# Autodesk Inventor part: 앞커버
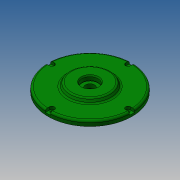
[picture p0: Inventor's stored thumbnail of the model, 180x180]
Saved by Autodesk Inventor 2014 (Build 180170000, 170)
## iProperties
Created: 2016-11
Part Number: 앞커버
Material: 알루미늄 6061
Document SubType Name: Modeling
Designer: mduedu
Density: 2.71 g/cm^3
Mass: 394.831 g
Surface Area: 366.671 cm^2
Volume: 145.694 cm^3
Appearance: 진녹색
Author: mduedu
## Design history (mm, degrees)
sketch "스케치1"
  geometry: L1 (22, -12.5)-(22, -30); L2 (22, -30)-(16, -33.464); L3 (16, -33.464)-(16, -65); L4 (16, -65)-(8, -65); L5 (8, -65)-(8, -53); L6 (8, -53)-(0, -53); L7 (0, -53)-(0, -14); L8 (0, 0)-(22, 0); L9 (8, -14)-(8, -7); L10 (8, -7)-(14.5, -7); L11 (14.5, -7)-(14.5, -12.5); L12 (0, -14)-(8, -14); L13 (14.5, -12.5)-(22, -12.5)
  constraints: 26 end point, 8 parallel, 3 perpendicular, 2 horizontal, 2 vertical alignment, 1 collinear
  dimensions: "d0" = 8 distance of L5.end L6.end; "d2" = 8 distance of L3.end L4.end; "d3" = 6 distance between parallel lines of L1 L3; "d4" = 120 deg angle of L3 L2; "d5" = 7.5 distance of L11.end L1.start; "d6" = 60 diameter of L1.end L8; "d7" = 14 diameter of L10 L8; "d8" = 28 diameter of L12 L8; "d9" = 25 diameter of L13 L8; "d10" = 106 diameter of L6 L8; "d11" = 130 diameter of L4 L8
revolve "회전1" sketch "스케치1" stored, may be unused: angle "d12" = 90 deg
fillet "모깎기1" dims "d13" = 0.3
fillet "모깎기2" dims "d14" = 3
chamfer "모따기1" distance "d15" = 1; stored, may be unused: second distance "d16" = 2, angle "d17" = 45 deg
fillet "모깎기3" dims "d18" = 0.3
chamfer "모따기2" distance "d36" = 2; stored, may be unused: second distance "d37" = 2, angle "d38" = 30 deg
sketch "스케치3"
  geometry: C1 r 65 at (0, 0) reference; A1 r 59 centre (0, 0) between (0, 59) and (59, 0); 2 further points
  constraints: 4 point on circle, 2 horizontal alignment, 2 vertical alignment, 1 centre point, 1 coincident
  dimensions: "d33" = 118 diameter of A1
sketch "스케치4"
  geometry: 4 further points
  constraints: 4 other
hole "구멍2" sketch "스케치4" at (0, 59), (-59, 0), (59, 0), (0, -59) diameter "d39" = 4.5; stored, may be unused: countersink angle "d43" = 90 deg, drill point angle "d45" = 0 deg; dims "d40" = 6, "d41" = 8, "d42" = 4.6, "d44" = 8
sketch "스케치6"
  geometry: L1 (-4, 5.877)-(-4, 0); L2 (4, 5.877)-(4, 0); A1 r 4 centre (0, 0) between (-2.712, 2.941) and (2.712, 2.941) reference; A2 r 65 centre (0, -59) between (-4, 5.877) and (4, 5.877) reference; 1 further point
  constraints: 4 end point, 4 point on circle, 2 tangent, 2 vertical
extrude "돌출2" cut sketch "스케치6" stored distance "d51" = 10; taper "d52" = 0 deg
sketch "스케치5"
  geometry: C1 r 22 at (0, 0); C2 r 45 at (0, 0); 1 further point
  constraints: 2 centre point, 2 coincident
  dimensions: "d46" = 44 diameter of C1; "d47" = 90 diameter of C2
extrude "돌출1" cut sketch "스케치5" distance "d48" = 8; taper "d49" = 0 deg
fillet "모깎기4" dims "d50" = 3
node "솔리드1"
pattern_circular "원형 패턴1" dims angle "d54" = 360 deg
